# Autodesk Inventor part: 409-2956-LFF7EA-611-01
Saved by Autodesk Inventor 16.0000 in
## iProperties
Created: 2010-06
Part Number: 409-2956-LFF7EA-611-01
Cost Center: 0 lbmass
Material: A36 STEEL PLATE
Document SubType Name: Sheet Metal
Designer: S. Boerckel
Authority: 0 in^3
Mass: 46255 g
Surface Area: 9704.36 cm^2
Volume: 5884.86 cm^3
Density: 7.86 g/cm^3
Sheet Metal Rule: 1/2 HR PLATE
Description: PUMP MOUNT PLATE
Flat Pattern Width: 38.1 cm
Flat Pattern Length: 121.92 cm
Flat Pattern Area: 4645.15 cm^2
Sheet Metal Width: 47.0000 in
Sheet Metal Length: 752.0000 in^2
User Status: BURN/DRILL
SaveDate: 2008-01-15
SaveTime: 10:24
FileName: Sheet Metal
Wide: =<Flat Pattern Width>cm
Length: =<Flat Pattern Length>cm
Thickness: 0.5000 in
SMR: =<Sheet Metal Rule> - <Material>
Author: S. Boerckel
Revision Number: 0
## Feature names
1. Hole1
2. Plate1
